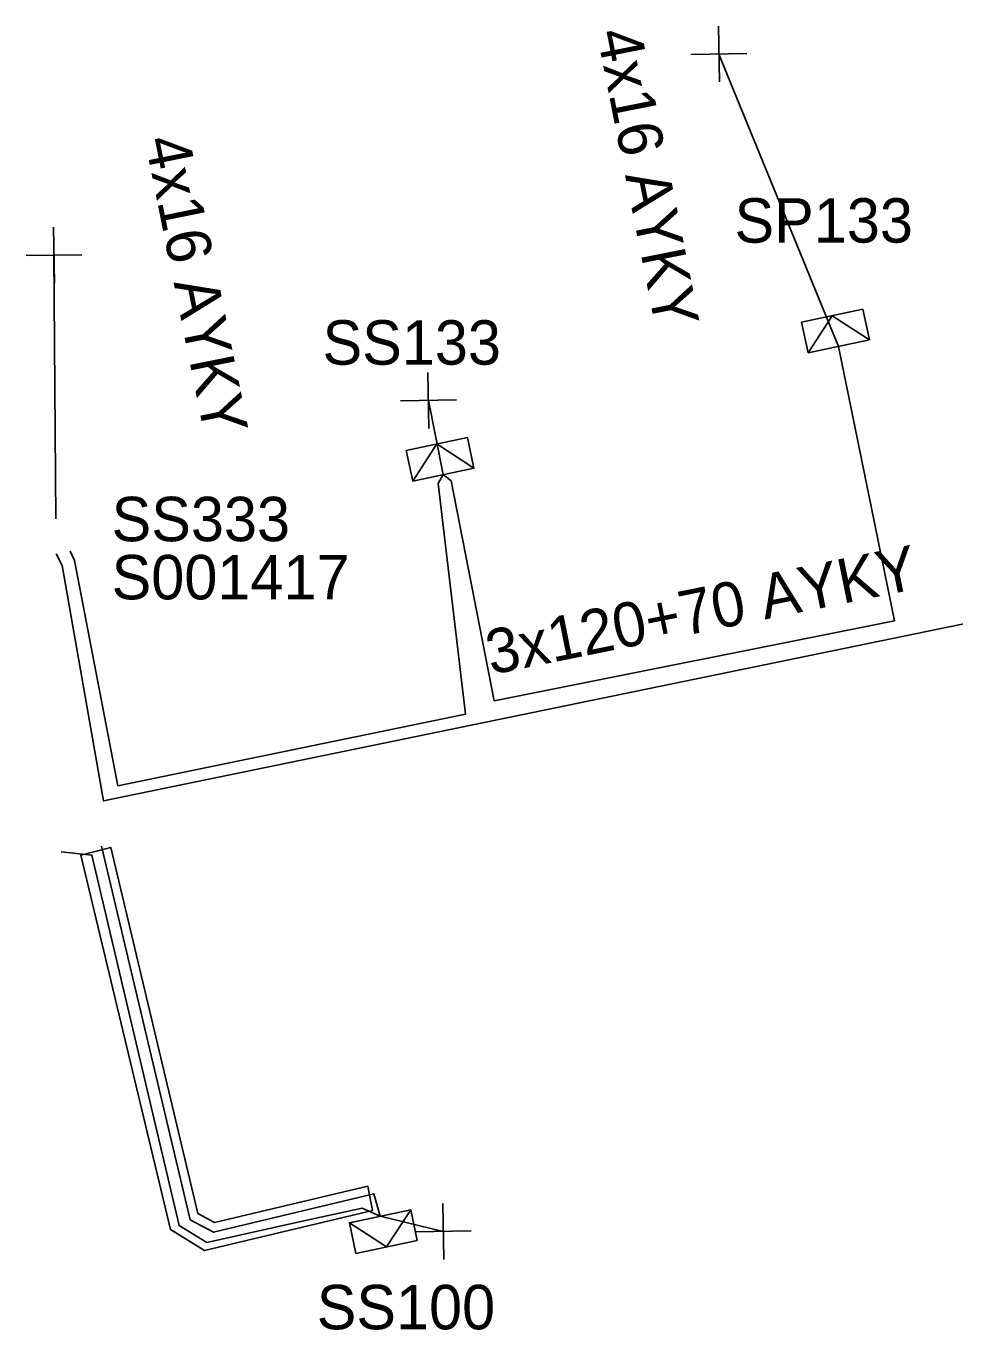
# Model space of a CAD drawing. Extents: x -762500 to -761285, y -1155006 to -1154135.
# Drawn here: x -762391.76 to -762370.97, y -1154707.54 to -1154678.38 of the extents above; entities that cross this region are included whole.
import ezdxf

# ---------------------------------------------------------------- set-up
doc = ezdxf.new("R2010")
doc.units = 0
for name, color, linetype in [('Vrstva 20', 7, 'Continuous'), ('Vrstva 29', 7, 'Continuous'), ('Vrstva 30', 7, 'Continuous'), ('Vrstva 31', 7, 'Continuous'), ('Vrstva 33', 7, 'Continuous'), ('Vrstva 34', 7, 'Continuous'), ('Vrstva 5', 7, 'Continuous'), ('Vrstva 59', 7, 'Continuous'), ('Vrstva 6', 7, 'Continuous')]:
    doc.layers.add(name, color=color, linetype=linetype)

msp = doc.modelspace()

# ---------------------------------------------------------------- linework, layer by layer
at = {"layer": 'Vrstva 20'}
msp.add_lwpolyline([(-762384, -1154704.87), (-762384.11, -1154704.33), (-762387.54, -1154705.14), (-762387.91, -1154704.94), (-762389.86, -1154696.75), (-762390.53, -1154696.92), (-762388.52, -1154705.3), (-762387.76, -1154705.77)], close=True, dxfattribs=at)
at = {"layer": 'Vrstva 31'}
for points in [[(-762373.028, -1154684.708), (-762374.398, -1154684.999)], [(-762373.028, -1154684.708), (-762372.883, -1154685.393), (-762374.252, -1154685.684), (-762374.398, -1154684.999)], [(-762373.713, -1154684.854), (-762374.252, -1154685.684)], [(-762373.713, -1154684.854), (-762372.883, -1154685.393)], [(-762381.878, -1154687.579), (-762383.247, -1154687.87)], [(-762381.878, -1154687.579), (-762381.732, -1154688.263), (-762383.102, -1154688.554), (-762383.247, -1154687.87)], [(-762382.562, -1154687.724), (-762383.102, -1154688.554)], [(-762382.562, -1154687.724), (-762381.732, -1154688.263)], [(-762384.372, -1154705.831), (-762384.518, -1154705.147), (-762383.148, -1154704.856), (-762383.003, -1154705.54)], [(-762383.688, -1154705.686), (-762383.148, -1154704.856)], [(-762383.688, -1154705.686), (-762384.518, -1154705.147)], [(-762384.372, -1154705.831), (-762383.003, -1154705.54)]]:
    msp.add_lwpolyline(points, dxfattribs=at)
at = {"layer": 'Vrstva 34'}
for points in [[(-762376.239, -1154679.625), (-762376.261, -1154678.375)], [(-762376.875, -1154679.011), (-762375.625, -1154678.989)], [(-762391.119, -1154684.125), (-762391.141, -1154682.875)], [(-762391.755, -1154683.511), (-762390.505, -1154683.489)], [(-762382.739, -1154687.375), (-762382.761, -1154686.125)], [(-762383.375, -1154686.761), (-762382.125, -1154686.739)], [(-762382.409, -1154705.965), (-762382.431, -1154704.715)], [(-762383.045, -1154705.351), (-762381.795, -1154705.329)]]:
    msp.add_lwpolyline(points, dxfattribs=at)
at = {"layer": 'Vrstva 5'}
for points in [[(-762391.08, -1154690.18), (-762390.95, -1154690.44), (-762390.02, -1154695.71), (-762350.07, -1154687.49), (-762351.11, -1154682.27), (-762351.13, -1154682.11)], [(-762390.77, -1154690.12), (-762390.67, -1154690.33), (-762389.7, -1154695.37), (-762381.92, -1154693.77), (-762382.53, -1154688.61), (-762382.42, -1154688.41), (-762382.24, -1154688.55), (-762381.28, -1154693.47), (-762372.32, -1154691.68), (-762373.57, -1154685.54)], [(-762390.07, -1154696.72), (-762388.08, -1154705.08), (-762387.56, -1154705.36), (-762383.97, -1154704.5), (-762383.83, -1154705), (-762384.23, -1154704.82), (-762385.47, -1154705.09), (-762387.71, -1154705.59), (-762388.33, -1154705.21), (-762390.28, -1154696.92), (-762390.97, -1154696.85)]]:
    msp.add_lwpolyline(points, dxfattribs=at)
at = {"layer": 'Vrstva 59'}
for points in [[(-762373.57, -1154685.54), (-762376.25, -1154679)], [(-762391.09, -1154689.4), (-762391.13, -1154683.5)], [(-762382.42, -1154688.41), (-762382.75, -1154686.75)], [(-762383.83, -1154705), (-762382.42, -1154705.34)]]:
    msp.add_lwpolyline(points, dxfattribs=at)

# ---------------------------------------------------------------- texts
at = {"layer": 'Vrstva 29'}
msp.add_text('S001417', height=0.9943, dxfattribs=at).set_placement((-762389.84, -1154691.2))
at = {"layer": 'Vrstva 30'}
msp.add_text('SS333', height=0.9943, dxfattribs=at).set_placement((-762389.84, -1154689.9))
at = {"layer": 'Vrstva 33'}
for s, p in [('SP133', (-762375.9, -1154683.22)), ('SS133', (-762385.12, -1154685.95)), ('SS100', (-762385.25, -1154707.53))]:
    msp.add_text(s, height=0.9943, dxfattribs=at).set_placement(p)
at = {"layer": 'Vrstva 6'}
for s, height, rotation, p in [('4x16 AYKY', 0.9943, 281.2952, (-762378.99, -1154678.52)), ('4x16 AYKY', 0.9943, 281.4186, (-762389.1, -1154680.92)), ('3x120+70 AYKY', 0.99429, 11.4182, (-762381.35, -1154692.89))]:
    msp.add_text(s, height=height, rotation=rotation, dxfattribs=at).set_placement(p)

doc.saveas('drawing.dxf')
